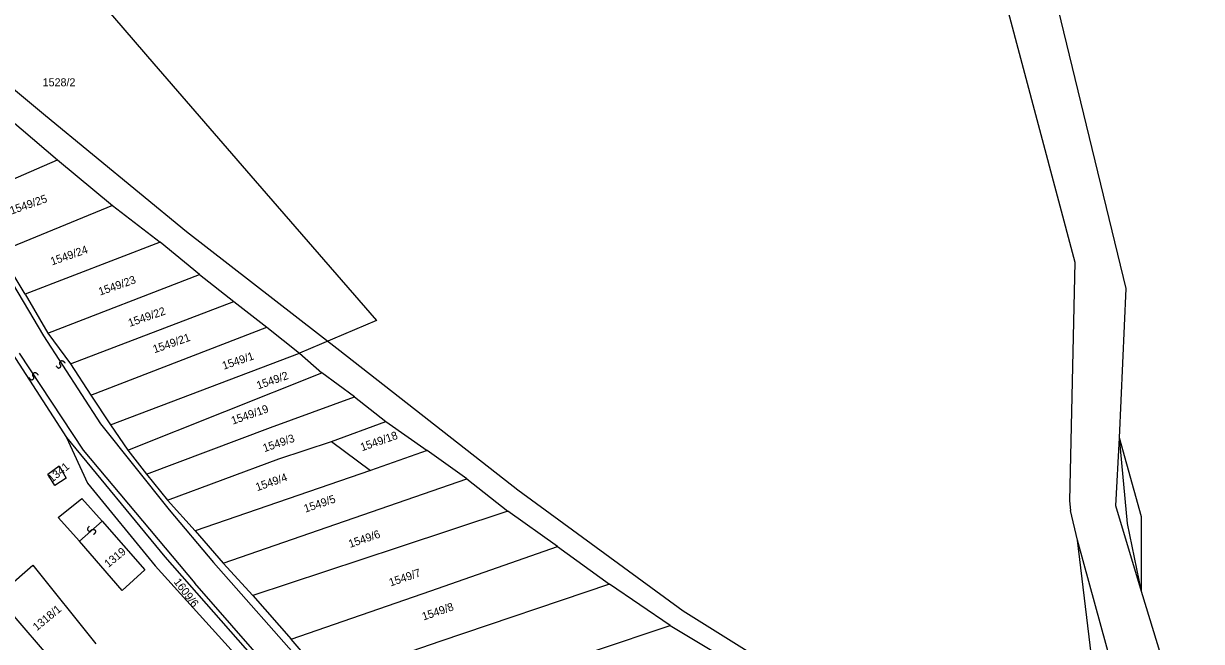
# Model space of a CAD drawing. Extents: x -581999 to -572728, y -1219553 to -1212032.
# Drawn here: x -578955.2 to -578660.9, y -1215170.4 to -1215016 of the extents above; entities that cross this region are included whole.
import ezdxf

# ---------------------------------------------------------------- set-up
doc = ezdxf.new("R2010")
doc.units = 0
for name, color, linetype in [('Vrstva 1', 7, 'Continuous'), ('Vrstva 2', 7, 'Continuous'), ('Vrstva 4', 7, 'Continuous'), ('Vrstva 6', 7, 'Continuous'), ('Vrstva 63', 7, 'Continuous')]:
    doc.layers.add(name, color=color, linetype=linetype)

msp = doc.modelspace()

# ---------------------------------------------------------------- linework, layer by layer
at = {"layer": 'Vrstva 1'}
for p, q in [((-578679.667, -1215082.144), (-578721.153, -1214911.9)), ((-578681.347, -1215119.523), (-578679.667, -1215082.144)), ((-578958.013, -1215098.527), (-578944.479, -1215119.383)), ((-578944.479, -1215119.383), (-578919.923, -1215149.19)), ((-578944.479, -1215119.383), (-578939.257, -1215130.828)), ((-578682.26, -1215136.493), (-578681.347, -1215119.523)), ((-578679.33, -1215140.871), (-578681.347, -1215119.523)), ((-578675.873, -1215139.249), (-578681.347, -1215119.523)), ((-578949.179, -1215128.533), (-578946.339, -1215126.484)), ((-578946.339, -1215126.484), (-578944.592, -1215129.557)), ((-578947.431, -1215131.401), (-578949.179, -1215128.533)), ((-578944.592, -1215129.557), (-578947.431, -1215131.401)), ((-578939.257, -1215130.828), (-578922.339, -1215151.457)), ((-578946.558, -1215139.39), (-578940.661, -1215134.678)), ((-578675.873, -1215157.895), (-578682.26, -1215136.493)), ((-578675.873, -1215157.895), (-578675.873, -1215139.249)), ((-578675.873, -1215157.895), (-578679.33, -1215140.871)), ((-578682.235, -1215179.915), (-578691.869, -1215145.091)), ((-578959.662, -1215157.212), (-578952.891, -1215151.272)), ((-578952.891, -1215151.272), (-578937.167, -1215170.938)), ((-578924.936, -1215152.501), (-578930.615, -1215157.622)), ((-578660.875, -1215206.543), (-578675.873, -1215157.895)), ((-578945.684, -1215177.903), (-578960.098, -1215161.105))]:
    msp.add_line(p, q, dxfattribs=at)
for points in [[(-578718.677, -1214977.311), (-578692.487, -1215075.606)], [(-578994.95, -1215005.239), (-578957.813, -1214985.184), (-578922.725, -1215026.083)], [(-578922.725, -1215026.083), (-578897.348, -1215055.292), (-578867.046, -1215090.204), (-578886.277, -1215098.335)], [(-578964.985, -1215034.527), (-578946.743, -1215050.019)], [(-578968.804, -1215059.641), (-578946.743, -1215050.019)], [(-578946.743, -1215050.019), (-578933.005, -1215061.452)], [(-578933.005, -1215061.452), (-578961.245, -1215072.987)], [(-578933.005, -1215061.452), (-578921.115, -1215070.595)], [(-578921.115, -1215070.595), (-578954.808, -1215083.56)], [(-578911.272, -1215078.705), (-578921.115, -1215070.595)], [(-578954.808, -1215083.56), (-578961.245, -1215072.987)], [(-578692.487, -1215075.606), (-578693.888, -1215135.208), (-578693.56, -1215137.617)], [(-578949.203, -1215093.351), (-578911.272, -1215078.705)], [(-578911.272, -1215078.705), (-578902.675, -1215085.431)], [(-578954.808, -1215083.56), (-578949.203, -1215093.351)], [(-578943.511, -1215101.035), (-578902.675, -1215085.431)], [(-578902.675, -1215085.431), (-578894.415, -1215091.823)], [(-578938.397, -1215108.87), (-578894.415, -1215091.823)], [(-578894.415, -1215091.823), (-578886.277, -1215098.335)], [(-578949.203, -1215093.351), (-578943.511, -1215101.035)], [(-578933.527, -1215116.215), (-578886.277, -1215098.335)], [(-578886.277, -1215098.335), (-578880.69, -1215103.245)], [(-578943.511, -1215101.035), (-578938.397, -1215108.87)], [(-578929.146, -1215122.581), (-578880.69, -1215103.245)], [(-578872.58, -1215109.24), (-578880.69, -1215103.245)], [(-578938.397, -1215108.87), (-578933.527, -1215116.215)], [(-578924.524, -1215128.582), (-578893.535, -1215116.915), (-578872.58, -1215109.24)], [(-578872.58, -1215109.24), (-578864.688, -1215115.382)], [(-578933.527, -1215116.215), (-578929.146, -1215122.581)], [(-578878.254, -1215120.42), (-578864.688, -1215115.382)], [(-578864.688, -1215115.382), (-578854.372, -1215122.634)], [(-578919.294, -1215135.074), (-578891.457, -1215124.729), (-578878.254, -1215120.42)], [(-578878.254, -1215120.42), (-578868.541, -1215127.668)], [(-578929.146, -1215122.581), (-578924.524, -1215128.582)], [(-578854.372, -1215122.634), (-578868.541, -1215127.668)], [(-578844.448, -1215129.73), (-578854.372, -1215122.634)], [(-578868.541, -1215127.668), (-578912.39, -1215142.766)], [(-578924.524, -1215128.582), (-578919.294, -1215135.074)], [(-578905.366, -1215150.819), (-578844.448, -1215129.73)], [(-578844.448, -1215129.73), (-578834.256, -1215137.833)], [(-578940.661, -1215134.678), (-578935.625, -1215140.323), (-578924.936, -1215152.501)], [(-578919.294, -1215135.074), (-578912.39, -1215142.766)], [(-578930.615, -1215157.622), (-578941.275, -1215145.282), (-578946.558, -1215139.39)], [(-578834.256, -1215137.833), (-578861.62, -1215146.932), (-578897.953, -1215158.905)], [(-578821.774, -1215146.658), (-578834.256, -1215137.833)], [(-578686.339, -1215190.639), (-578691.869, -1215145.091), (-578693.56, -1215137.617)], [(-578912.39, -1215142.766), (-578905.366, -1215150.819)], [(-578888.366, -1215169.784), (-578853.493, -1215157.681), (-578821.774, -1215146.658)], [(-578821.774, -1215146.658), (-578808.812, -1215156.089)], [(-578922.339, -1215151.457), (-578883.644, -1215194.262), (-578872.07, -1215207.223)], [(-578919.923, -1215149.19), (-578881.59, -1215192.788), (-578870.137, -1215206.089)], [(-578897.953, -1215158.905), (-578905.366, -1215150.819)], [(-578808.812, -1215156.089), (-578851.181, -1215170.339), (-578877.029, -1215179.32)], [(-578793.678, -1215166.381), (-578808.812, -1215156.089)], [(-578897.953, -1215158.905), (-578888.366, -1215169.784)], [(-578869.31, -1215191.673), (-578793.678, -1215166.381)], [(-578793.678, -1215166.381), (-578779.862, -1215174.619)], [(-578879.392, -1215180.289), (-578888.366, -1215169.784)]]:
    msp.add_lwpolyline(points, dxfattribs=at)
at = {"layer": 'Vrstva 4'}
for p, q in [((-578983.39, -1215038.228), (-578950.279, -1215093.994)), ((-578950.279, -1215093.994), (-578936.02, -1215115.983)), ((-578956.321, -1215098.301), (-578940.371, -1215122.557)), ((-578936.02, -1215115.983), (-578918.861, -1215137.518)), ((-578940.371, -1215122.557), (-578912.431, -1215155.764)), ((-578918.861, -1215137.518), (-578907.744, -1215150.666)), ((-578941.275, -1215145.282), (-578935.625, -1215140.323)), ((-578907.744, -1215150.666), (-578832.193, -1215236.239)), ((-578851.527, -1215225.365), (-578912.431, -1215155.764))]:
    msp.add_line(p, q, dxfattribs=at)
at = {"layer": 'Vrstva 6'}
for points in [[(-578947.147, -1215101.475), (-578946.667, -1215102.182), (-578945.973, -1215101.871), (-578945.896, -1215101.471), (-578946.132, -1215101.126), (-578946.217, -1215100.794), (-578946.135, -1215100.504), (-578945.991, -1215100.324), (-578945.755, -1215100.196), (-578945.39, -1215100.232), (-578944.963, -1215100.671), (-578944.908, -1215100.844)], [(-578953.889, -1215104.432), (-578953.409, -1215105.139), (-578952.715, -1215104.828), (-578952.638, -1215104.428), (-578952.874, -1215104.083), (-578952.959, -1215103.751), (-578952.877, -1215103.461), (-578952.733, -1215103.281), (-578952.497, -1215103.153), (-578952.132, -1215103.189), (-578951.705, -1215103.628), (-578951.65, -1215103.801)], [(-578938.855, -1215141.593), (-578939.442, -1215142.215), (-578938.987, -1215142.824), (-578938.581, -1215142.812), (-578938.295, -1215142.507), (-578937.989, -1215142.353), (-578937.689, -1215142.369), (-578937.482, -1215142.471), (-578937.306, -1215142.674), (-578937.261, -1215143.038), (-578937.596, -1215143.55), (-578937.754, -1215143.642)]]:
    msp.add_open_spline(points, degree=2, dxfattribs=at)
at = {"layer": 'Vrstva 63'}
for p, q in [((-578949.764, -1215039.006), (-578964.586, -1215026.76)), ((-578914.505, -1215067.993), (-578949.764, -1215039.006)), ((-578876.214, -1215097.766), (-578914.505, -1215067.993)), ((-578831.747, -1215132.595), (-578876.214, -1215097.766)), ((-578790.424, -1215162.817), (-578831.747, -1215132.595)), ((-578719.345, -1215206.971), (-578790.424, -1215162.817))]:
    msp.add_line(p, q, dxfattribs=at)

# ---------------------------------------------------------------- texts
at = {"layer": 'Vrstva 2'}
msp.add_text('1528/2', height=2, dxfattribs=at).set_placement((-578950.467, -1215031.662))
for s, rotation, p in [('1549/25', 19.24967, (-578958.277, -1215063.726)), ('1549/24', 19.24967, (-578948.119, -1215076.429)), ('1549/23', 19.24967, (-578936.121, -1215083.971)), ('1549/22', 19.24967, (-578928.704, -1215091.796)), ('1549/21', 19.24967, (-578922.517, -1215098.374)), ('1549/1', 18.94287, (-578905.213, -1215102.493)), ('1549/2', 19.24967, (-578896.614, -1215107.421)), ('1549/19', 19.24967, (-578902.96, -1215116.213)), ('1549/3', 19.24967, (-578895.046, -1215123.088)), ('1549/18', 19.24967, (-578870.668, -1215122.858)), ('1341', 39.56521, (-578948.172, -1215130.781)), ('1549/4', 19.24967, (-578896.855, -1215132.836)), ('1549/5', 18.94287, (-578884.812, -1215138.212)), ('1549/6', 18.94287, (-578873.645, -1215146.998)), ('1319', 39.56521, (-578934.046, -1215152.032)), ('1549/7', 18.94287, (-578863.522, -1215156.652)), ('1609/6', 306.99397, (-578917.821, -1215155.5)), ('1318/1', 39.56521, (-578951.925, -1215167.826)), ('1549/8', 18.94287, (-578855.28, -1215165.155))]:
    msp.add_text(s, height=2, rotation=rotation, dxfattribs=at).set_placement(p)

doc.saveas('drawing.dxf')
